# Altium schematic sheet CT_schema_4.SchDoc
size 304 x 319 mm
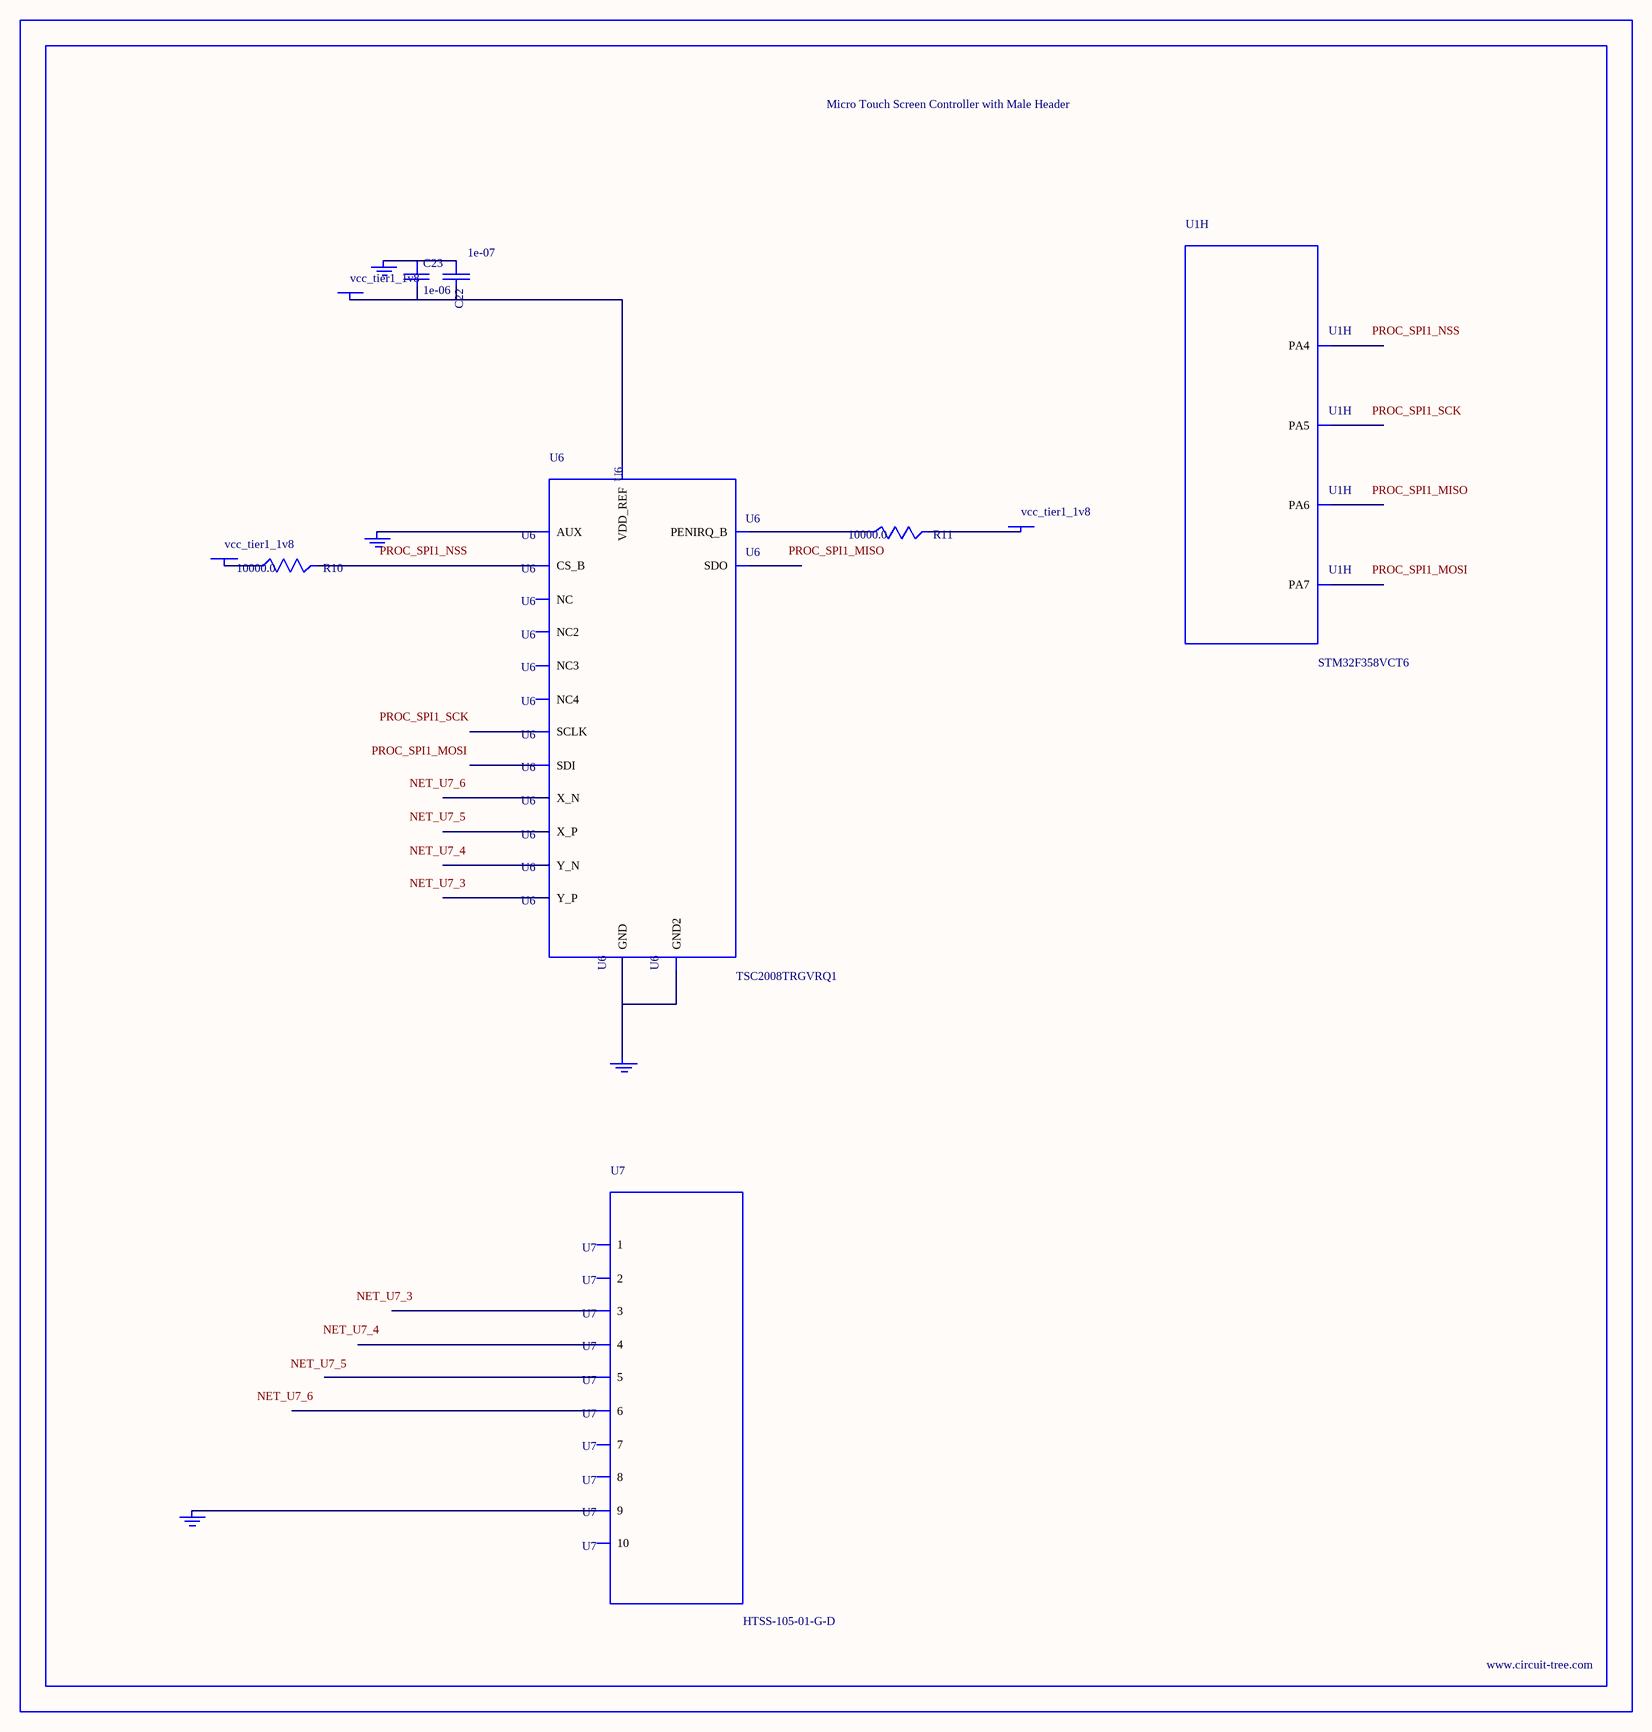
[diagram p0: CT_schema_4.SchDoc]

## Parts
BORDER3  (no value)
C22  1e-07  [C0402]
C23  1e-06  [C0603]
GND_INSTANCE_3_0  (no value)
GND_INSTANCE_3_1  (no value)
GND_INSTANCE_3_2  (no value)
GND_INSTANCE_3_3  (no value)
POWER_INSTANCE_3_0  vcc_tier1_1v8
POWER_INSTANCE_3_1  vcc_tier1_1v8
POWER_INSTANCE_3_2  vcc_tier1_1v8
R10  10000.0  [R0603]
R11  10000.0  [R0603]
U1  STM32F358VCT6  [LQFP100]  (part H of 10)
U6  TSC2008TRGVRQ1  [QFN65P400X400X100-17N]
U7  HTSS-105-01-G-D  [HTSS-105-01-G-D]

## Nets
NetC22_1: C22.1 C23.1 GND_INSTANCE_3_0.0(GND)
NetC22_2: C22.2 C23.2 POWER_INSTANCE_3_1.0(PWR) U6.5(VDD_REF)
NetGND_INSTANCE_3_1_0: GND_INSTANCE_3_1.0(GND) U6.12(AUX)
NetGND_INSTANCE_3_2_0: GND_INSTANCE_3_2.0(GND) U6.10(GND) U6.17(GND2)
NetGND_INSTANCE_3_3_0: GND_INSTANCE_3_3.0(GND) U7.9
NetPOWER_INSTANCE_3_0_0: POWER_INSTANCE_3_0.0(PWR) R10.1
NetPOWER_INSTANCE_3_2_0: POWER_INSTANCE_3_2.0(PWR) R11.2
NetR10_2: R10.2 U6.3(CS_B)
NetR11_1: R11.1 U6.15(PENIRQ_B)

Not connected (* = marked no-connect by the designer): U1 29(PA4) 30(PA5) 31(PA6) 32(PA7); U6 1(NC) 2(SDI) 4(SCLK) 6(X_P) 7(Y_P) 8(X_N) 9(Y_N) 11(NC2) 13(NC3) 14(NC4) 16(SDO); U7 1 2 3 4 5 6 7 8 10

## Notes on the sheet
- Labels drawn without touching a wire or pin: NET_U7_3, NET_U7_4, NET_U7_5, NET_U7_6, PROC_SPI1_MISO, PROC_SPI1_MOSI, PROC_SPI1_NSS, PROC_SPI1_SCK

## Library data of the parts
BORDER3 = BORDER_PAGE3
C22 = C0402C104K3RACTU
C23 = C0603C105K3RACTU
GND_INSTANCE_3_0-GND_INSTANCE_3_3 = GND
POWER_INSTANCE_3_0-POWER_INSTANCE_3_2 = PWR
R10 R11 = RC0603JR-0710KL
